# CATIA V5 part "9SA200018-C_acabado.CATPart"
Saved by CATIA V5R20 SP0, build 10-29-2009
Part number: 9SA200018-C_acabado
Revision: ANY
Definition: UNKNOWN
Nomenclature: 9SA200018-C_acabado
Source: Unknown
Bounding box of the stored display mesh (mm): x -10 to 10, y 0 to 18, z -10 to 10
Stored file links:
  C:\Users\Utente\Desktop\IO LAVORO\3D X SITO CF\CUMSA\3D files SA\SA 200518\9SA200018-C_acabado.CATPart
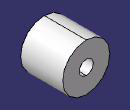
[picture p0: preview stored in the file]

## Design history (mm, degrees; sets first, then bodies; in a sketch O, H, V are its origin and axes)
Body1 "Envolver1" (main body)
  Solid1: solid without history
